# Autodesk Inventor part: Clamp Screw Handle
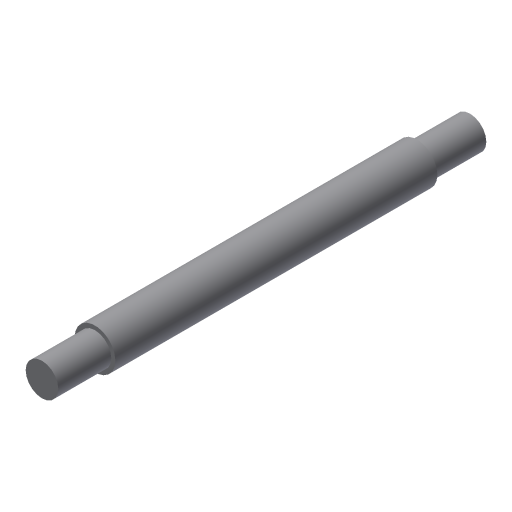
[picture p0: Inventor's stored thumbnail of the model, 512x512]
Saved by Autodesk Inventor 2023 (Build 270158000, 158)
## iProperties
Created: 2002-02
Part Number: Clamp Screw Handle
Document SubType Name: Modeling
Designer: ***
Density: 1 g/cm^3
Material: Generic
Appearance: Default
Control State: 0
Master: False
Checked Out: False
Shininess: 77.0
Length Units: 11269
Angle Units: 11279
Time Units: 11290
Mass Units: 11283
Length Display Precision: 3
Angle Display Precision: 2
Compacted: True
Density: 0.0
Volumn: 0.0
Area: 0.0
PropertySet Name: Model Information
Author: ***
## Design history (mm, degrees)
sketch "Sketch1"
  geometry: L1 (0, 105)-(4, 105); L2 (4, 105)-(4, 92); L3 (4, 92)-(5, 92); L4 (5, 92)-(5, 13); L5 (5, 13)-(4, 13); L6 (4, 13)-(4, 0); L7 (4, 0)-(0, 0); L8 (0, 0)-(0, 105)
  constraints: 16 end point, 5 parallel, 2 equal length, 1 collinear, 1 horizontal, 1 perpendicular
  dimensions: "d0" = 10 diameter of L4 L8; "d1" = 8 diameter of L2 L8; "d2" = 13 distance of L1.end L2.end; "d3" = 79 distance of L3.end L4.end
revolve "Revolution1" sketch "Sketch1" stored, may be unused: angle "d4" = 90 deg
body "Solid1"
